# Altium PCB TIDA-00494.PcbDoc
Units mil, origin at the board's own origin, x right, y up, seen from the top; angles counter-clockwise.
Board outline 3140 x 3140 mil, 2 copper layers (Top Layer, Bottom Layer), stack 62 mil thick; 48 components, 40 nets, 138 pads, 74 vias.
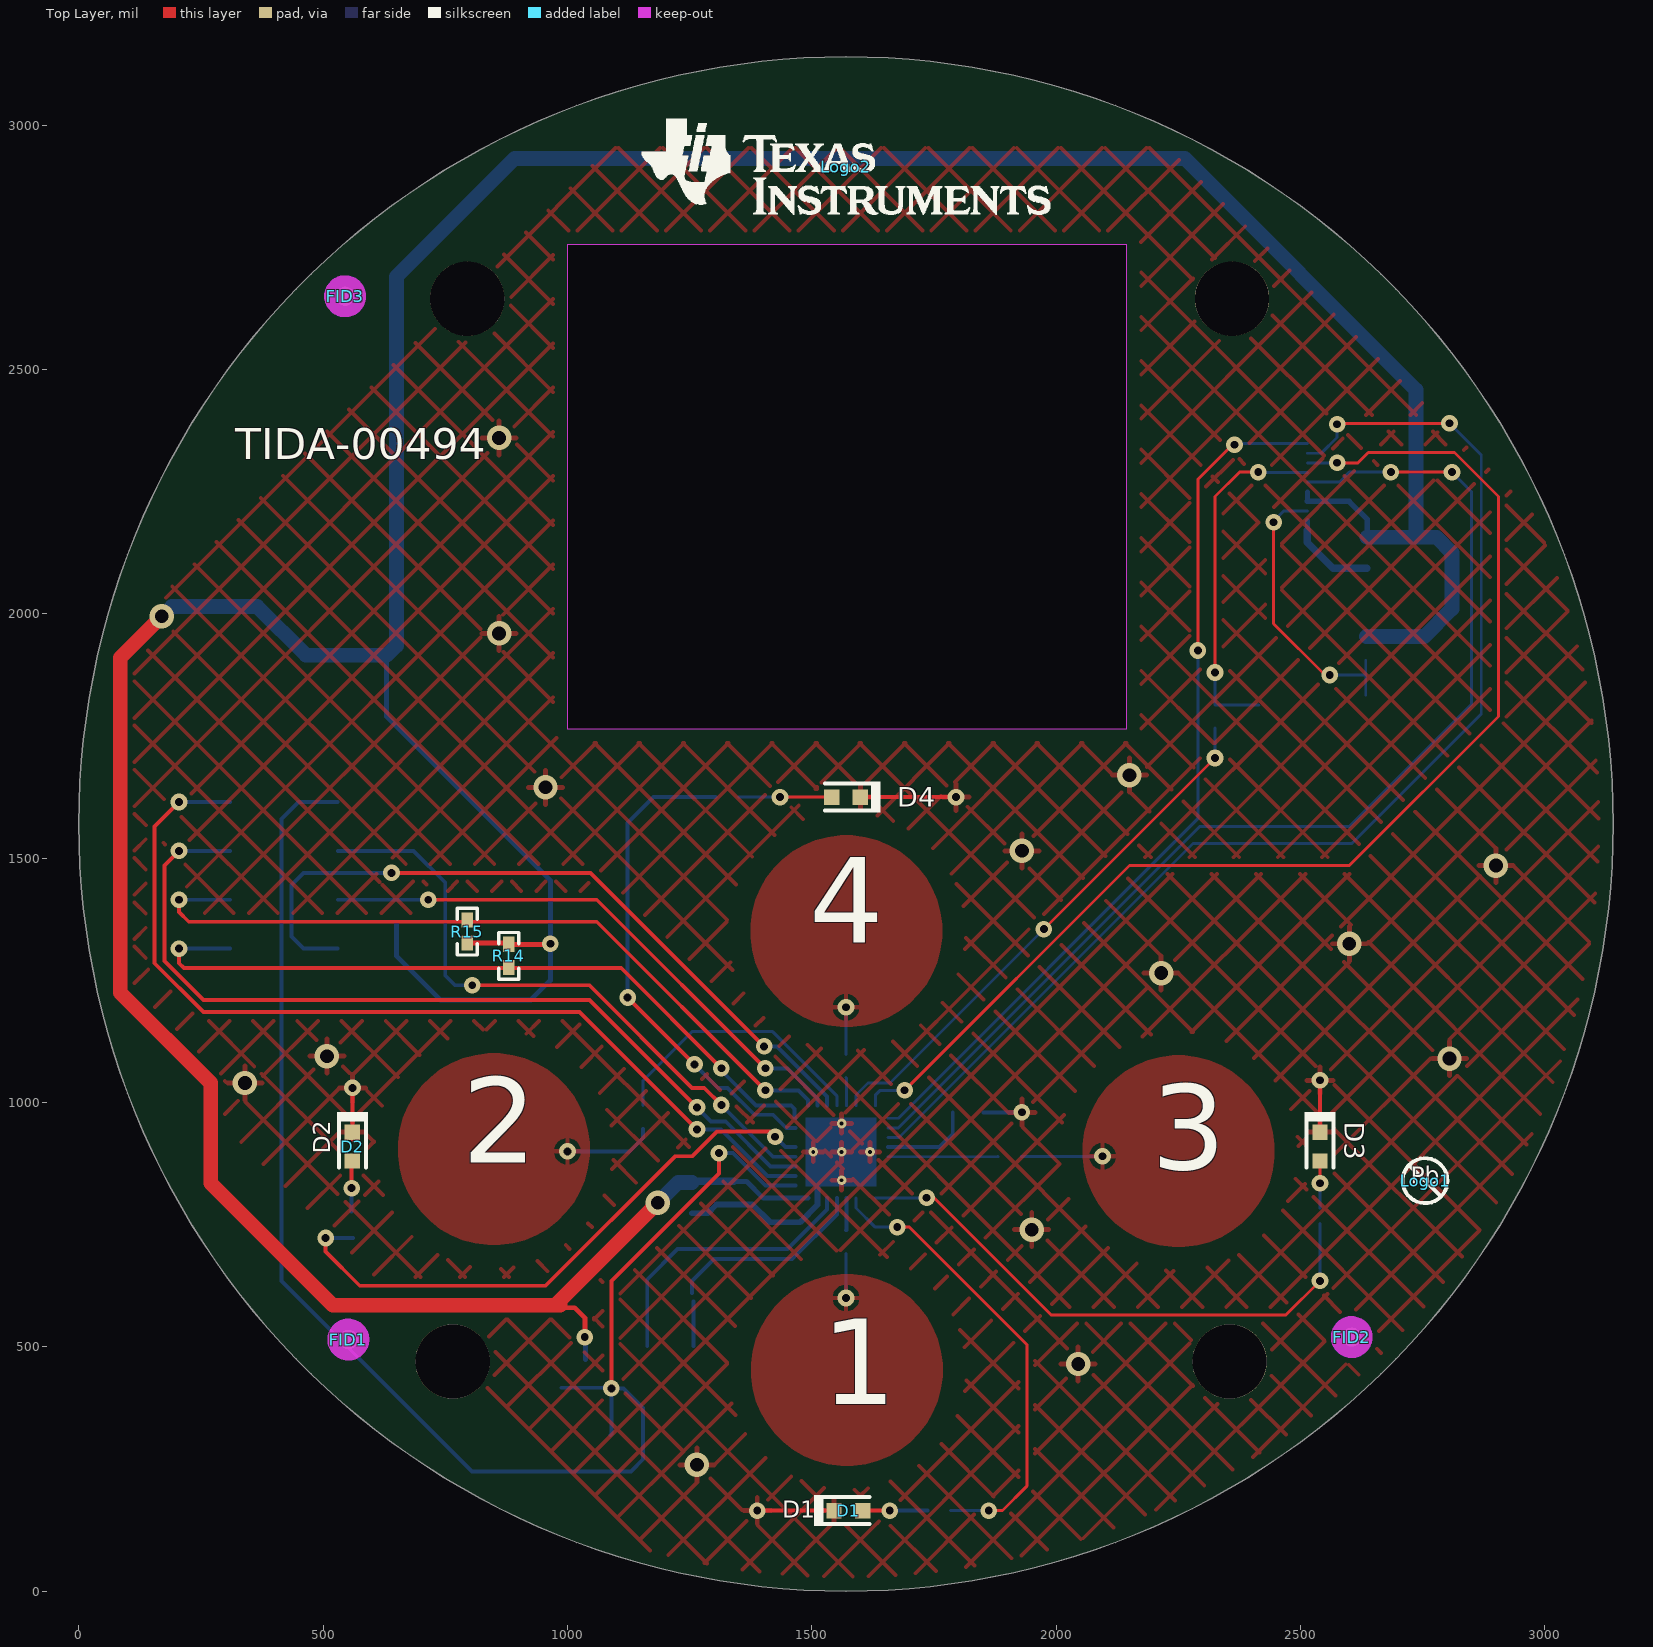
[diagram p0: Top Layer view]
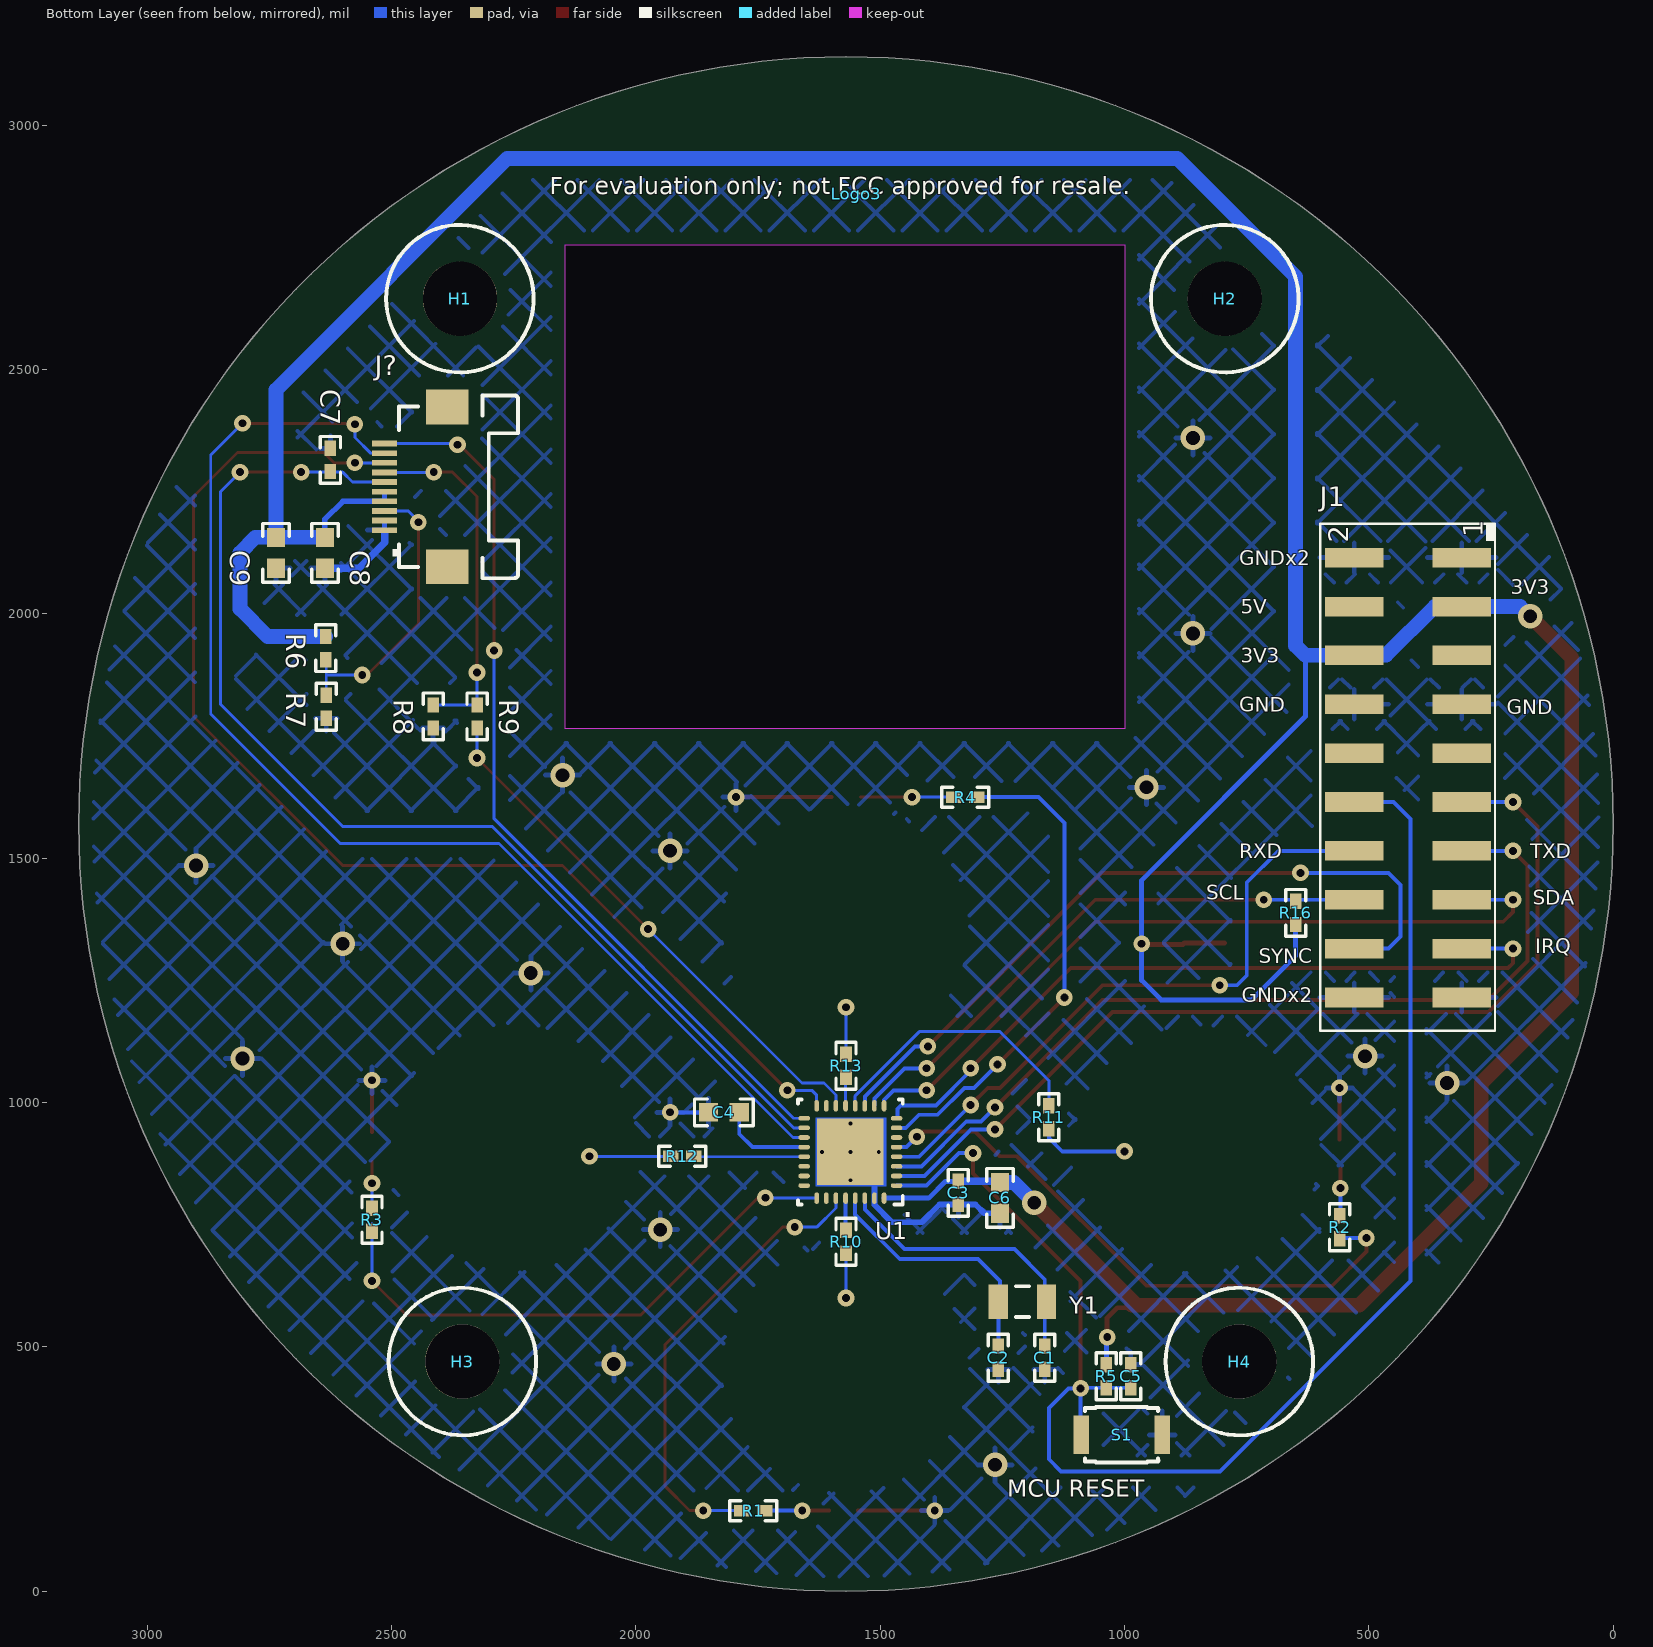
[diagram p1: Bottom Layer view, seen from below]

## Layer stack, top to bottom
Top Solder: solder mask 0.4, Solder Resist, Dk 3.5
Top Layer: signal copper 1.4
Dielectric1: core 59.2, FR-4, Dk 4.2
Bottom Layer: signal copper 1.4
Bottom Solder: solder mask 0.4, Solder Resist, Dk 3.5

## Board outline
1570,0 cw(c1570,1570) 0,1570 cw(c1570,1570) 1570,3140 cw(c1570,1570) 3140,1570 cw(c1570,1570)
cut-out: 1000,1765 2145,1765 2145,2755 1000,2755

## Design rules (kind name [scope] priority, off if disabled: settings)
AcuteAngle [All] p1: minimum=4.50000000000000E+0001 checktracksonly=FALSE
AssemblyTestPointUsage [All] p1: valid=2
BoardOutlineClearance BoardOutlineClearance_MountingHoles [OnCopper and InComponentClass('Mounting Holes')] p1: gap=40
BoardOutlineClearance BoardOutlineClearance_Poly [OnCopper and InPoly] p2: gap=25
BoardOutlineClearance [OnCopper and Not InComponentClass('Logo') and not InComponentClass('FiducialMark') and not InRegion(1000,500,4000,800)] p3: gap=25
Clearance Clearance_1 [InNamedPolygon('GND_L01_P076')] p1: gap=10 except(45: Poly-Poly)
Clearance Clearance_Keepouts [((IsTrack Or IsArc) And Not InPoly) And IsFree and IsKeepOut vs ((IsTrack Or IsArc) And Not InPoly) And IsFree and IsKeepOut] p2: gap=0
Clearance Clearance_Poly [InPolygon] p3: gap=25
Clearance [All] p4: gap=7.87
ComponentClearance ComponentClearance_MountingHoles_FiducialMarks [InComponentClass('Mounting Holes') vs InComponentClass('FiducialMark')] p1: gap=50 collisioncheckmode=3 verticalgap=10 showdistances=FALSE
ComponentClearance ComponentClearance_Shunt [InComponentClass('Header') vs InComponentClass('Shunt')] p2: gap=0 collisioncheckmode=3 verticalgap=0 showdistances=FALSE
ComponentClearance ComponentClearance_Logo [InComponentClass('Logo')] p3: gap=50 collisioncheckmode=3 verticalgap=10 showdistances=FALSE
ComponentClearance ComponentClearance_ScrewToNut [(HasFootprint('NY PMS 440 0025 PH')) vs (HasFootprint('Keystone_1902C'))] p4: gap=5 collisioncheckmode=3 verticalgap=10 showdistances=FALSE
ComponentClearance ComponentClearance_MountingHoles [InComponentClass('Mounting Holes')] p5: gap=250 collisioncheckmode=3 verticalgap=100000 showdistances=FALSE
ComponentClearance ComponentClearance_SmallPassives [HasFootprint('0201*') or HasFootprint('0402*') or HasFootprint('0508') or HasFootprint('0603*') or HasFootprint('0612') or HasFootprint('0805*') or HasFootprint('0815*') or HasFootprint('0830*') or HasFootprint('1206*') or HasFootprint('1210*') or HasFootprint('1808*') or HasFootprint('1812*') or HasFootprint('1825*') or HasFootprint('2010*') or HasFootprint('2220*') or HasFootprint('2225*') or HasFootprint('2512*') or HasFootprint('2728*') or HasFootprint('3518*') vs HasFootprint('0201*') or HasFootprint('0402*') or HasFootprint('0508') or HasFootprint('0603*') or HasFootprint('0612') or HasFootprint('0805*') or HasFootprint('0815*') or HasFootprint('0830*') or HasFootprint('1206*') or HasFootprint('1210*') or HasFootprint('1808*') or HasFootprint('1812*') or HasFootprint('1825*') or HasFootprint('2010*') or HasFootprint('2220*') or HasFootprint('2225*') or HasFootprint('2512*') or HasFootprint('2728*') or HasFootprint('3518*')] p6: gap=14.96 collisioncheckmode=3 verticalgap=10 showdistances=FALSE
ComponentClearance ComponentClearance_THtoSMT [IsThruComponent vs IsSMTComponent] p7: gap=40 collisioncheckmode=3 verticalgap=30 showdistances=FALSE
ComponentClearance ComponentClearance_THtoTH [IsThruComponent vs IsThruComponent] p8: gap=30 collisioncheckmode=3 verticalgap=30 showdistances=FALSE
ComponentClearance [All] p9: gap=30 collisioncheckmode=3 verticalgap=10 showdistances=FALSE
DiffPairsRouting [All] p1: maxlimit=100 minlimit=10 mostfreqgap=10 toplayer_minwidth=15 toplayer_maxwidth=15 toplayer_prefwidth=15 bottomlayer_minwidth=15 bottomlayer_maxwidth=15 bottomlayer_prefwidth=15 maxuncoupledlength=1000
FabricationTestPointUsage TestPointUsage [All] p1: valid=2 allowmultiple=FALSE
FabricationTestpoint Testpoint [All] p1: side=3 testpointundercomponent=TRUE minsize=40 maxsize=100 preferedsize=60 minholesize=0 maxholesize=40 preferedholesize=32 testpointgrid=1 allowsidetop=TRUE allowsidebottom=TRUE usegrid=TRUE gridtolerance=0.01
FanoutControl Fanout_LCC [IsLCC] p1: bgadir=Out bgaviamode=Centered fanoutstyle=Auto fanoutdirection=Alternating viagrid=1 // Fanout_LCC (Default Rule)
FanoutControl Fanout_BGA [IsBGA] p2: bgadir=Out bgaviamode=Centered fanoutstyle=Auto fanoutdirection=Alternating viagrid=1 // Fanout_BGA (Default Rule)
FanoutControl Fanout_Default [All] p4: bgadir=Out bgaviamode=Centered fanoutstyle=Auto fanoutdirection=Alternating viagrid=1 // Fanout_Default (Default Rule)
FanoutControl Fanout_Small [(CompPinCount < 5)] p5: bgadir=Out bgaviamode=Centered fanoutstyle=Auto fanoutdirection=OutThenIn viagrid=1 // Fanout_Small (Default Rule)
Height [All] p1 off: minheight=0 maxheight=1000 prefheight=500
HoleSize [All] p1: absolutevalues=TRUE maxlimit=251 minlimit=7.87 maxpercent=80.000 minpercent=20.000
MinimumAnnularRing MinimumAnnularRing_ThermalPadVias [IsVia and InAnyComponent] p1: minimumring=5.91
MinimumAnnularRing [All] p2: minimumring=8
MinimumSolderMaskSliver MinimumSolderMaskSliver_Logo [InComponentClass('Logo') vs InComponentClass('Logo')] p1: minsoldermaskwidth=0.7
MinimumSolderMaskSliver [All] p2: minsoldermaskwidth=3.94
PlaneConnect [All] p1: planeconnectstyle=Relief reliefexpansion=10 reliefentries=4 reliefconductorwidth=10 reliefairgap=10
PolygonConnect [All] p1: connectstyle=Relief reliefconductorwidth=10 reliefentries=4 polygonreliefangle="90 Angle" airgapwidth=10
RoutingVias ThermalPadVias [IsVia and InAnyComponent] p1: holewidth=7.87 width=19.68 viastyle="Through Hole" minholewidth=7.87 minwidth=19.68 maxholewidth=12.99 maxwidth=23.62
RoutingVias [All] p2: holewidth=16 width=34 viastyle="Through Hole" minholewidth=7.87 minwidth=26 maxholewidth=40 maxwidth=65
SilkToBoardRegionClearance [Not ((IsComment or IsDesignator) And (Hide <> 'False')) and not InRegion(1000,500,4000,800)] p1:
SilkToSilkClearance SilkToSilkClearance_Pb-FreeLogo [(HasFootprint('Pb-Free_Overlay_Medium') OR HasFootprint('Pb-Free_Overlay_Small')) vs (HasFootprint('Pb-Free_Overlay_Medium') OR HasFootprint('Pb-Free_Overlay_Small'))] p1: silktosilkclearance=0
SilkToSilkClearance [All] p2: silktosilkclearance=4
SilkToSolderMaskClearance SilkToComponentPadClearance [IsPad and InAnycomponent] p1: minsilkscreentomaskgap=5 clearancetoexposedcopper=TRUE
SilkToSolderMaskClearance "Silk to Solder Mask Opening" [All] p2: minsilkscreentomaskgap=4 clearancetoexposedcopper=FALSE
SolderMaskExpansion [All] p1: expansion=1.97
Width [All] p1: maxlimit=100 minlimit=6 preferedwidth=10 checkconnectedcopper=TRUE
14 further rules are at their usual default settings.

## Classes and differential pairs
net class R16_Nets: MSP_SCL VCC_MSP
net class R15_Nets: MSP_SDA VCC_MSP
net class R14_Nets: MSP_IRQ VCC_MSP
component class FiducialMark: FID1 FID2 FID3
component class TIDA-00494_Hardware: FID1 FID2 FID3 H1 H2 H3 H4 Logo1 Logo2 Logo3 ZZ1 ZZ2 ZZ3 ZZ4
net class Y1_Nets: XIN XOUT
net class U1_Nets: DISP_CLK DISP_CS DISP_EN DISP_EXTCOMIN DISP_SI EZFET_SBWTCK_TST EZFET_SBWTDIO_RST GND MSP_IRQ MSP_RXD MSP_SCL MSP_SDA MSP_SYNC MSP_TXD NetR10_1 NetR11_1 NetR12_1 NetR13_1 P1.0/LED4 P1.6/LED2 P2.7/LED3 P3.2/LED1 VCC_MSP VREG XIN XOUT
net class S1_Nets: EZFET_SBWTDIO_RST GND
net class R5_Nets: EZFET_SBWTDIO_RST VCC_MSP
net class R4_Nets: NetD4_1 P1.0/LED4
net class R3_Nets: NetD3_1 P2.7/LED3
net class C7_Nets: DISP_EN GND
net class J1_Nets: EZFET_RXD EZFET_SBWTCK_TST EZFET_SBWTDIO_RST EZFET_TXD GND MSP_IRQ MSP_RXD MSP_SCL MSP_SDA MSP_SYNC MSP_TXD VCC_5V VCC_METERED VCC_MSP
net class D2_Nets: GND NetD2_1
net class D1_Nets: GND NetD1_1
net class C2_Nets: GND XOUT
net class C5_Nets: EZFET_SBWTDIO_RST GND
net class C4_Nets: GND VREG
net class C3_Nets: GND VCC_MSP
net class C6_Nets: GND VCC_MSP
net class C1_Nets: GND XIN
component class TIDA-00494_Schematic: C1 C2 C3 C4 C5 C6 C7 C8 C9 D1 D2 D3 D4 J1 J? R1 R2 R3 R4 R5 R6 R7 R8 R9 R10 R11 R12 R13 R14 R15 R16 S1 U1 Y1
component class AssemblyNote: ZZ1 ZZ2 ZZ3 ZZ4
component class Logo: Logo2
net class C8_Nets: GND VCC_MSP
net class C9_Nets: GND VCC_MSP
net class D3_Nets: GND NetD3_1
net class D4_Nets: GND NetD4_1
net class J?_Nets: DISP_CLK DISP_CS DISP_EN DISP_SI GND NetJ?_3 NetJ?_7 VCC_MSP
net class R1_Nets: NetD1_1 P3.2/LED1
pad class "Through Hole": C5-2 D1-2 D2-2 J2-19 J2-20 TP4-1
net class R2_Nets: NetD2_1 P1.6/LED2
net class R6_Nets: NetJ?_3 VCC_MSP
net class R7_Nets: GND NetJ?_3
net class R8_Nets: GND NetJ?_7
net class R9_Nets: DISP_EXTCOMIN NetJ?_7
net class R10_Nets: BUTTON1 NetR10_1
net class R11_Nets: BUTTON2 NetR11_1
net class R12_Nets: BUTTON3 NetR12_1
net class R13_Nets: BUTTON4 NetR13_1

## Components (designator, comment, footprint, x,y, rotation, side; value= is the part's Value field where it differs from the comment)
C1 "GRM1555C1H220JA01D" 0402 1163.21,477.72 r270 bottom
C2 "GRM1555C1H220JA01D" 0402 1258.21,477.72 r270 bottom
C3 "C1005X5R1A104K" 0402 1340,815 r270 bottom
C4 "C1608X5R1A105K" 0603 1820,980 r0 bottom
C5 "C1005X7R1H102K" 0402 987.36,440 r90 bottom
C6 "C0603C475K8PACTU" 0603 1255,805 r270 bottom
C7 "C1005X5R1A104K" 0402 2625,2315 r90 bottom
C8 "C1608X5R1A105K" 0603 2636.3,2125 r90 bottom
C9 "C1608X5R1A105K" 0603 2736.3,2125 r90 bottom
D1 "LTST-C190GKT" LED_LTST-C190 1575,165 r180 top
D2 "LTST-C190GKT" LED_LTST-C190 560,910 r90 top
D3 "LTST-C190GKT" LED_LTST-C190 2540,910 r90 top
D4 "LTST-C190GKT" LED_LTST-C190 1570,1625 r0 top
FID1 "Fiducial" Fiducial10-20 551.67,515 r90 top
FID2 "Fiducial" Fiducial10-20 2605,520 r0 top
FID3 "Fiducial" Fiducial10-20 545,2650 r90 top
H1 "4826" KEYSTONE_4826 2360,2645 r90 bottom
H2 "4826" KEYSTONE_4826 795,2645 r90 bottom
H3 "4826" KEYSTONE_4826 2355,470 r90 bottom
H4 "4826" KEYSTONE_4826 765,470 r90 bottom
J1 "SSW-110-22-F-D-VS-K" CONN_SSW-110-22-F-D-VS-K 420,1665 r90 bottom
J? "FH12A-10S-0.5SH(55)" Hirose_FH12A-10S-0_5SH[55] 2450.1,2260.04 r90 bottom
Logo1 "Pb-Free Symbol" Pb-Free_Overlay_Small 2755,840 r0 top
Logo2 "Texas Instruments" TI_Stacked_Overlay_Small 1570,2915 r0 top
Logo3 "FCC disclaimer" FCC_disclaimer 1548.75,2860 r180 bottom
R1 "CRCW0402390RJNED" 0402 1760,165 r0 bottom
R2 "CRCW0402390RJNED" 0402 560,745 r270 bottom
R3 "CRCW0402390RJNED" 0402 2540,760 r270 bottom
R4 "CRCW0402390RJNED" 0402 1326.2,1625 r180 bottom
R5 "CRCW040247K0JNED" 0402 1037.36,440 r90 bottom
R6 "CRCW040247K0JNED" 0402 2635,1930 r90 bottom
R7 "CRCW04020000Z0ED" 0402 2633.59,1810 r90 bottom
R8 "CRCW04020000Z0ED" 0402 2415,1790 r90 bottom
R9 "CRCW04020000Z0ED" 0402 2325,1790 r90 bottom
R10 "CRCW04021K00JNED" 0402 1570,715 r270 bottom
R11 "CRCW04021K00JNED" 0402 1155,970 r270 bottom
R12 "CRCW04021K00JNED" 0402 1905,890 r0 bottom
R13 "CRCW04021K00JNED" 0402 1570,1075 r90 bottom
R14 "CRCW040210K0JNED" 0402 880,1300 r90 top
R15 "CRCW04022K20JNED" 0402 795,1350 r270 top
R16 "CRCW04022K20JNED" 0402 650,1388 r270 bottom
S1 "SKRKAEE010" SW_SKRKAEE010 1005.55,320 r0 bottom
U1 "MSP430FR2633IRHB" RHB0032E 1561.06,898.94 r0 bottom locked
Y1 "FC-135 32.7680KA-A3" Epson_FC-135 1209,592.72 r0 bottom
ZZ1 "This Assembly Note is for PCB labels only" AssemblyNoteLabel -110,3680 r0 top
ZZ2 "These assemblies are ESD sensitive, ESD precautions shall be observed." AssemblyNote -110,3585 r0 top
ZZ3 "These assemblies must be clean and free from flux and all contaminants. Use of no clean flux is not acceptable." AssemblyNote -110,3480 r0 top
ZZ4 "These assemblies must comply with workmanship standards IPC-A-610 Class 2, unless otherwise specified." AssemblyNote -110,3380 r0 top

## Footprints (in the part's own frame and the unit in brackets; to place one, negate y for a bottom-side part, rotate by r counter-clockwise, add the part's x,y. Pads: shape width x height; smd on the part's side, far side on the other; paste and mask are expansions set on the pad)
0402 [mm] "0402 from SM-752 data"
  rect 0.8x0.6 smd: 1(-0.6,0) 2(0.6,0)
  silkscreen extent -1.22,-0.52 1.22,0.52, body extent -0.55,-0.3 0.55,0.3, height 0.6
0603 [mm] "0603 from SM-752 data"
  rect 1x0.95 smd: 1(-0.8,0) 2(0.8,0)
  silkscreen extent -1.52,-0.69 1.52,0.69, body extent -0.87,-0.47 0.87,0.47, height 0.85
AssemblyNote [mil] "Assembly Note"
AssemblyNoteLabel [mil] "Assembly Note for PCB Labels"
CONN_SSW-110-22-F-D-VS-K [mil]
  rect 40x120 smd: 1(450,-110) 2(450,110) 3(350,-110) 4(350,110) 5(250,-110) 6(250,110) 7(150,-110) 8(150,110) 9(50,-110) 10(50,110) 11(-50,-110) 12(-50,110) 13(-150,-110) 14(-150,110) 15(-250,-110) 16(-250,110) 17(-350,-110) 18(-350,110) 19(-450,-110) 20(-450,110)
  silkscreen extent -518,-178 520,179, body extent -510,-155 500,155, height 435
Epson_FC-135 [mm] "SMD, 2-Leads, Body 3.2x1.5mm"
  rect 1x1.8 smd: 1(-1.25,0) 2(1.25,0)
  silkscreen extent -0.35,-0.8 0.35,0.8, body extent -1.65,-0.8 1.65,0.8, height 0.9
FCC_disclaimer [mil]
Fiducial10-20 [mm]
  round 1 smd mask+0.5: 1(0,0)
  Top Layer keep-out circle w1.178: c0,0 r0.5
Hirose_FH12A-10S-0_5SH[55] [mm] "FFC Connector , Top, 0.5mm, 10x1, R/A, SMT"
  rect 0.3x1.3 smd: 1(-2.254,1.625) 2(-1.754,1.625) 3(-1.254,1.625) 4(-0.754,1.625) 5(-0.253,1.625) 6(0.246,1.625) 7(0.746,1.625) 8(1.246,1.625) 9(1.746,1.625) 10(2.247,1.625)
  rect 1.8x2.2 smd: MP1(-4.15,-1.625) MP2(4.15,-1.625)
  silkscreen extent -4.75,-5.31 4.75,1.22, body extent -4.75,-5.31 4.75,1.69, height 2
KEYSTONE_4826 [mil] "HEX STANDOFF 6-32 NYLON 1750 mil"
  round 1 on Mech4: 0(0,0)
  round 152 hole 152 unplated: MH(0,0)
  silkscreen extent -151,-151 151,151, body extent -144,-125 144,125, height 1751
LED_LTST-C190 [mm] "Lite-On"
  rect 0.8x0.8 smd: 1(-0.75,0) 2(0.75,0)
  silkscreen extent -1.1,-0.8 1.8,0.8, body extent -0.85,-0.45 0.85,0.45, height 0.9
Pb-Free_Overlay_Small [mil]
  silkscreen extent -46,-46 46,46
RHB0032E [mm] "QFN, 32-Leads, Body 5x5mm, Pitch 0.5mm, Thermal Pad 3.45x3.45mm, TI Recommended"
  oval 0.6x0.24 smd: 1(-2.4,1.75) 2(-2.4,1.25) 3(-2.4,0.75) 4(-2.4,0.25) 5(-2.4,-0.25) 6(-2.4,-0.75) 7(-2.4,-1.25) 8(-2.4,-1.75) 17(2.4,-1.75) 18(2.4,-1.25) 19(2.4,-0.75) 20(2.4,-0.25) 21(2.4,0.25) 22(2.4,0.75) 23(2.4,1.25) 24(2.4,1.75)
  oval 0.24x0.6 smd: 9(-1.75,-2.4) 10(-1.25,-2.4) 11(-0.75,-2.4) 12(-0.25,-2.4) 13(0.25,-2.4) 14(0.75,-2.4) 15(1.25,-2.4) 16(1.75,-2.4) 25(1.75,2.4) 26(1.25,2.4) 27(0.75,2.4) 28(0.25,2.4) 29(-0.25,2.4) 30(-0.75,2.4) 31(-1.25,2.4) 32(-1.75,2.4)
  rect 3.45x3.45 smd paste-1.725: 33(0,0)
  silkscreen extent -2.72,-2.73 2.72,2.73, body extent -2.57,-2.57 2.58,2.58, height 1.01
SW_SKRKAEE010 [mm] "Alps recommended land pattern"
  rect 0.8x2 smd: 1(-2.1,0) 2(2.1,0)
  silkscreen extent -1.9,-1.44 1.92,1.44, body extent -2.4,-1.45 2.4,1.45, height 1.96
TI_Stacked_Overlay_Small [mil]
  silkscreen extent -418,-98 418,98

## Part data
C1 C2: "CAP, CERM, 22 pF, 50 V, +/- 5%, C0G/NP0, 0402"
C3 C7: "CAP, CERM, 0.1uF, 10V, +/-10%, X5R, 0402"
C4 C8 C9: "CAP, CERM, 1 µF, 10 V, +/- 10%, X5R, 0603"
C5: "CAP, CERM, 1000pF, 50V, +/-10%, X7R, 0402"
C6: "CAP, CERM, 4.7 µF, 10 V, +/- 10%, X5R, 0603"
D1 D2 D3 D4: "LED, Green, SMD"
FID1 FID2 FID3: "Fiducial mark.  There is nothing to buy or mount."
H1 H2 H3 H4: "HEX STANDOFF 6-32 NYLON 1-3/4\""
J1: "Connector, Receptacle, 100mil, 10x2, Gold plated, SMD"
J?: "FFC Connector , Top, 0.5mm, 10x1, R/A, SMT"
Logo1: library part Pb-Free
Logo2: library part TI_Logo, "Texas Instrument Corporate Signature"
Logo3: library part FCC_disclaimer, "FCC_disclaimer"
R1 R2 R3 R4: "RES, 390 ohm, 5%, 0.063W, 0402"
R5: "RES, 47k ohm, 5%, 0.063W, 0402"
R6: "RES, 47 k, 5%, 0.063 W, 0402"
R7 R8 R9: "RES, 0, 5%, 0.063 W, 0402"
R10 R11 R12 R13: "RES, 1.0 k, 5%, 0.063 W, 0402"
R14: "RES, 10 k, 5%, 0.063 W, 0402"
R15 R16: "RES, 2.2 k, 5%, 0.063 W, 0402"
S1: "Switch, Push Button, SMD"
U1: "MSP430 Captivate Microcontroller"
Y1: "Crystal, 32.768 KHz, 12.5 pF, SMD"
ZZ1: library part AssemblyNoteLabel
ZZ2 ZZ3 ZZ4: library part AssemblyNote

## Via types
v1: diameter 34, hole 16, Top Layer to Bottom Layer, 49 vias
v2: diameter 50, hole 28, Top Layer to Bottom Layer, 16 vias
v3: diameter 19.68, hole 7.87, Top Layer to Bottom Layer, 5 vias
v4: diameter 34, hole 16, Top Layer to Bottom Layer, tented both sides, 4 vias

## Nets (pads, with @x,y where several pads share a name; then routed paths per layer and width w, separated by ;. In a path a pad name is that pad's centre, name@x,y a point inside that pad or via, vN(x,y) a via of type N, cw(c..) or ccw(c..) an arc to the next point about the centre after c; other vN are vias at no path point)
BUTTON1: R10.2 | length 91.4
  Bottom Layer w6: v4(1570,600) R10.2
BUTTON2: R11.2 | length 185.2
  Bottom Layer w8: v4(1000,900) 1127.41,900 1155,927.59 R11.2
BUTTON3: R12.2 | length 166.4
  Bottom Layer w6: R12.2 v4(2095,890)
BUTTON4: R13.2 | length 96.4
  Bottom Layer w6: R13.2 v4(1570,1195)
DISP_CLK: J?.10 U1.17 | length 1837.6
  Top Layer w6: v1(2290,1925) 2290,2275 2360.94,2345.94 v1(2365,2345.94)
  Bottom Layer w6: U1.17 1677.18,967.83 2290,1580.66 v1(2290,1925) ; v1(2365,2345.94) 2365,2346.89 2366.56,2348.44 J?.10@2514.01,2348.44
DISP_CS: J?.8 U1.16 | length 2504.7
  Top Layer w6: v1(1690,1025) 2150,1485 2600,1485 2905,1790 2905,2240.25 2815.25,2330 2638.87,2330 2617.95,2309.07 v1(2575,2309.07)
  Bottom Layer w6: U1.16 1629.96,1014.96 1640,1025 v1(1690,1025) ; J?.8@2514.01,2309.07 v1(2575,2309.07)
DISP_EN: C7.1 J?.6 U1.18 | length 2349.5
  Top Layer w6: v1(2685,2290) v1(2810,2290)
  Bottom Layer w6: U1.18 1677.11,948.15 2293.97,1565 2600,1565 2850,1815 2850,2250 v1(2810,2290) ; J?.6@2514.01,2269.7 2579.7,2269.7 2600,2290 v1(2685,2290)
DISP_EXTCOMIN: R9.1 U1.14 | length 1103.5
  Top Layer w6: v1(1975,1355) 2315,1695 v1(2325,1705)
  Bottom Layer w6: U1.14 1590.59,1015.59 1615,1040 1660,1040 1970,1350 v1(1975,1355) ; v1(2325,1705) R9.1
DISP_SI: J?.9 U1.19 | length 2527.3
  Top Layer w6: v1(2575,2387.93) 2577.07,2390 v1(2805,2390)
  Bottom Layer w6: U1.19 1678.46,928.46 2280,1530 2605,1530 2870,1795 2870,2325 v1(2805,2390) ; J?.9@2514.01,2328.76 2542.61,2328.76 2575,2361.15 v1(2575,2387.93)
EZFET_RXD: J1.10
EZFET_SBWTCK_TST: J1.11 U1.2 | length 1947.6
  Top Layer w8: v1(205,1615) 155,1565 155,1285 255,1185 1025,1185 v1(1265,945)
  Bottom Layer w8: v1(205,1615) J1.11 ; v1(1265,945) 1313.94,945 1409.22,849.72 U1.2
EZFET_SBWTDIO_RST: C5.1 J1.12 R5.1 S1.2 U1.1 | length 3135
  Top Layer w8: v1(1090,415) 1090,635 1310,855 v1(1310,896.57)
  Bottom Layer w8: J1.12 450,1615 415,1580 415,635 805,245 1130,245 1155,270 1155,375 1115,415 v1(1090,415) ; C5.1 R5.1 1088.62,416.38 v1(1090,415) ; S1.2 1090,321.77 v1(1090,415) ; v1@1305,896.57 v1(1310,896.57) v1@1319.1,896.57 ; v1@1320,895.67 v1@1319.1,896.57 ; U1.1 1404.96,830.04 1338.43,896.57 v1@1319.1,896.57
EZFET_TXD: J1.9
GND: C1.2 C2.2 C3.2 C4.2 C5.2 C6.2 C7.2 C8.1 C9.1 D1.2 D2.2 D3.2 D4.2 J1.1 J1.2 J1.7 J1.8 J1.19 J1.20 J?.1 J?.2 R7.1 R8.1 S1.1 U1.31 U1.33 | length 1257.2
  Top Layer w8: D2.2@560,924.53 v1(560,1030) ; v1(1388.5,165) D1.2 ; D4.2 v1(1795,1625) ; D3.2 v1(2540,1045.45)
  Bottom Layer w8: C4.2 v1(1930,980)
  Bottom Layer w10: J?.1@2514.01,2171.28 J?.2@2514.01,2190.96
  Bottom Layer w12: C6.2 1287.32,773.5 1305.2,791.38 C3.2 1378.62,791.38 1415,755 1476.11,755 1511.85,790.74 U1.31 1511.85,849.72 v3(1561.06,898.94)
  Bottom Layer w15: v3(1619.13,898.94) U1.33@1622.32,898.94 ; J?.1@2514.01,2171.28 2514.01,2145.99 2566.5,2093.5 C8.1
  other v2: 1265,258.56 2045,465 1950,740 340,1040 2805,1090 507.83,1095 2215,1265 2600,1325 2900,1485 1930,1515 955,1645 2150,1670 860,1960 860,2360
  other v3: 1561.06,840.87 1502.99,898.94 1561.06,957.01
MSP_IRQ: J1.17 R14.1 U1.8 | length 1541.3
  Top Layer w8: v1(205,1315) 205,1285 215,1275 1110,1275 v1(1315,1070)
  Bottom Layer w8: v1(205,1315) J1.17 ; v1(1315,1070) 1315,1065 1385.9,994.1 1458.03,994.1 1465,987.13 1465,969.41 U1.8
MSP_RXD: J1.14 U1.4 | length 1293
  Top Layer w8: v1(805,1240) 1045,1240 1255,1030 1280,1030 v1(1315,995)
  Bottom Layer w8: J1.14 685,1515 750,1450 750,1260 770,1240 v1(805,1240) ; v1@1325,985 1420.91,889.09 U1.4
MSP_SCL: J1.16 R16.1 U1.10 | length 1165.1
  Top Layer w8: v1(715,1415) 1060,1415 v1(1405,1070)
  Bottom Layer w8: J1.16 v1(715,1415) ; v1(1405,1070) 1450,1070 1511.85,1008.15 U1.10
MSP_SDA: J1.15 R15.1 U1.9 | length 1601.6
  Top Layer w8: v1(205,1415) 205,1390 225,1370 1060,1370 v1(1405,1025)
  Bottom Layer w8: v1(205,1415) J1.15 ; v1@1405,1011.85 v1(1405,1025) 1472.55,1025 1492.17,1005.39 U1.9
MSP_SYNC: J1.18 U1.11 | length 1525.8
  Top Layer w8: v1(640,1470) 1047.5,1470 1052.5,1465 v1(1402.5,1115)
  Bottom Layer w8: J1.18 460,1315 435,1340 435,1445 455,1465 460,1470 v1(640,1470) ; v1(1402.5,1115) 1428.97,1115 1531.54,1012.43 U1.11
MSP_TXD: J1.13 U1.3 | length 1813.2
  Top Layer w8: v1(205,1515) 175,1485 175,1290 255,1210 1045,1210 v1(1265,990)
  Bottom Layer w8: v1(205,1515) J1.13 ; v1@1270,990 v1(1265,990) 1293.87,961.13 1323.87,961.13 1415.59,869.41 U1.3
NetD1_1: D1.1 R1.1 | length 131.9
  Top Layer w8: D1.1 v1(1659.55,165)
  Bottom Layer w8: v1(1659.55,165) R1.1
NetD2_1: D2.1 R2.1 | length 86.3
  Top Layer w8: v1(558.21,825) 558.21,863.68
  Bottom Layer w8: R2.1@558.21,777.38 v1(558.21,825)
NetD3_1: D3.1 R3.1 | length 96.9
  Top Layer w6: v1(2540,835) D3.1
  Bottom Layer w6: R3.1 v1(2540,835)
NetD4_1: D4.1 R4.1 | length 190.7
  Top Layer w6: v1(1435,1625) D4.1
  Bottom Layer w6: R4.1 v1(1435,1625)
NetJ?_3: J?.3 R6.1 R7.2 | length 591
  Top Layer w6: v1(2445,2187.5) 2445,1980 2550,1875 v1(2560,1875)
  Bottom Layer w6: v1(2445,2187.5) 2445,2190 2465.65,2210.65 J?.3@2514.01,2210.65 ; v1(2560,1875) 2633.59,1875 ; R7.2 2633.59,1875 ; R6.1@2633.59,1904.97 2633.59,1875
NetJ?_7: J?.7 R8.2 R9.2 | length 726.6
  Top Layer w6: v1(2325,1880) 2325,2240 2375,2290 v1(2413.78,2290) v1@2415,2288.78
  Bottom Layer w6: v1(2325,1880) R9.2 R8.2 ; v1@2415,2289.39 J?.7@2514.01,2289.39
NetR10_1: R10.1 U1.28 | length 66.2
  Bottom Layer w8: R10.1 1570.91,739.53 U1.28
NetR11_1: R11.1 U1.12 | length 563.7
  Bottom Layer w6: R11.1 1155,1045 1255,1145 1420,1145 1551.22,1013.78 U1.12
NetR12_1: R12.1 U1.21 | length 226.2
  Bottom Layer w6: U1.21 1880.47,889.09 R12.1
NetR13_1: R13.1 U1.13 | length 58.3
  Bottom Layer w6: R13.1 1570.91,1050.47 U1.13
P1.0/LED4: R4.2 U1.7 | length 1012.6
  Top Layer w8: v1(1123.15,1215) v1(1260,1078.15)
  Bottom Layer w8: v1(1123.15,1215) 1123.15,1572.45 1175.7,1625 R4.2 ; v1(1260,1078.15) 1308.15,1030 1327.55,1030 1382.55,975 1420.83,975 1447.68,948.15 U1.7
P1.6/LED2: R2.2 U1.5 | length 1226
  Top Layer w8: v1@505,729.86 505,695 575,625 955,625 1220,890 1255,890 1305.83,940.83 1414.17,940.83 v1(1425,930)
  Bottom Layer w8: v1(505,722.89) R2.2@561.51,722.89 ; v1(1425,930) 1446.22,908.78 U1.5
P2.7/LED3: R3.2 U1.25 | length 1155.8
  Top Layer w6: v1(1735,805) 1750,805 1990,565 2470,565 v1(2540,635)
  Bottom Layer w6: U1.25 1630.51,805 v1(1735,805) ; v1(2540,635) R3.2 2540,752.17
P3.2/LED1: R1.2 U1.27 | length 952.3
  Top Layer w6: v1(1675,745) 1700,745 1940,505 1940,215 1890,165 v1(1862,165)
  Bottom Layer w6: U1.27 1590.59,784.41 1630,745 v1(1675,745) ; R1.2 v1(1862,165)
VCC_5V: J1.4
VCC_METERED: J1.5
VCC_MSP: C3.1 C6.1 C8.2 C9.2 J1.3 J1.6 J?.4 J?.5 R5.2 R6.2 R14.2 R15.2 R16.2 U1.32 | length 8961.6
  Top Layer w10: R15.2 877.24,1326.38 R14.2 963.62,1323.62 v1(965,1325) ; 980,580 1015,580 1035.55,559.45 v1(1035.55,520) ; 985,585 985,590
  Top Layer w30: v2(170,1995) 85,1910 85,1225 270,1040 270,835 520,585 975,585 ; 985,585 975,585 ; v2(1185,795) 975,585
  Bottom Layer w10: 630,1915 630,1790 965,1455 v1(965,1325) 965,1250 925,1210 740,1210 650,1300 R16.2 ; v1(1035.55,520) 1037.2,518.35 R5.2@1037.2,473.62 ; C3.1 1366.38,838.62 1400.55,804.45 U1.32 ; J?.4@2514.01,2231.93 J?.5@2514.01,2250.02
  Bottom Layer w11: J?.4 2599.63,2230.37 2636.3,2193.7 C8.2
  Bottom Layer w15: C6.1 1257.13,838.62 C3.1
  Bottom Layer w30: v2(170,1995) 190,2015 J1.3 365,2015 465,1915 J1.6 630,1915 650,1935 650,2690.04 891.87,2931.91 2263.09,2931.91 2736.3,2458.7 C9.2 ; v2(1185,795) 1226.5,836.5 C6.1 ; R6.2 2753.62,1953.62 2810,2010 2810,2125 2778.5,2156.5 C9.2 ; C8.2 C9.2
VREG: C4.1 U1.20 | length 188.3
  Bottom Layer w8: U1.20 1761.48,908.78 1788.5,935.8 C4.1
XIN: C1.1 U1.30 Y1.1 | length 587.5
  Bottom Layer w8: C1.1 1163.21,638.21 1225,700 1450,700 1531.54,781.54 U1.30
XOUT: C2.1 U1.29 Y1.2 | length 502.3
  Bottom Layer w8: Y1.2@1255,610 1255,635 1300,680 1460,680 1551.22,771.22 U1.29 ; C2.1 Y1.2
pads on no net: FID1.1 FID2.1 FID3.1 H1.0 H1.MH H2.0 H2.MH H3.0 H3.MH H4.0 H4.MH J?.MP1 J?.MP2 U1.6 U1.15 U1.22 U1.23 U1.24 U1.26

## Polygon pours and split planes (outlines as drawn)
BUTTON4 on Top Layer "BUTTON4_L01_P070" (solid, pour order 70): 1374.58,1350.68 ccw(c1570.58,1350.68) 1570.58,1154.68 ccw(c1570.58,1350.68) 1766.58,1350.68 ccw(c1570.58,1350.68) 1570.58,1546.68 ccw(c1570.58,1350.68)
BUTTON1 on Top Layer "BUTTON1_L01_P068" (solid, pour order 68): 1375.68,452.65 ccw(c1571.68,452.65) 1571.68,256.65 ccw(c1571.68,452.65) 1767.68,452.65 ccw(c1571.68,452.65) 1571.68,648.65 ccw(c1571.68,452.65)
BUTTON3 on Top Layer "BUTTON3_L01_P066" (solid, pour order 66): 2054.68,900.5 ccw(c2250.68,900.5) 2250.68,704.5 ccw(c2250.68,900.5) 2446.68,900.5 ccw(c2250.68,900.5) 2250.68,1096.5 ccw(c2250.68,900.5)
BUTTON2 on Top Layer "BUTTON2_L01_P064" (solid, pour order 64): 653.32,904.5 ccw(c849.32,904.5) 849.32,708.5 ccw(c849.32,904.5) 1045.32,904.5 ccw(c849.32,904.5) 849.32,1100.5 ccw(c849.32,904.5)
GND on Top Layer "GND_L01_P076" (hatched 45Degree grid 64 track 8, remove dead copper, pour order 76): 70,1182.03 1249.05,2.98 2222.39,2.98 2227.39,7.98 3132.39,912.98 3132.39,2047.98 2227.39,2952.98 1087.98,2952.98 70,1935
GND on Bottom Layer "GND_L02_P074" (hatched 45Degree grid 64 track 8, remove dead copper, pour order 74): 0,1030 1030,0 2245,0 2250,5 3155,910 3155,2045 2250,2950 965,2950 0,1985

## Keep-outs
Keep-Out Layer:
  text ".Layer_Name" at -73,-1708.49 h60

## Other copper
Top Layer:
  text ".Layer_Name" at -73,-1708.49 h60
Bottom Layer:
  region net GND: 1487.4,955.87 1487.4,968.86 1518.75,968.86 1632.4,968.86 1632.4,828.86 1487.4,828.86
  pour cut-out: 1315.84,1355.8 ccw(c1570.84,1355.8) 1570.84,1100.8 ccw(c1570.84,1355.8) 1825.84,1355.8 ccw(c1570.84,1355.8) 1570.84,1610.8 ccw(c1570.84,1355.8)
  pour cut-out: 597.47,905 ccw(c852.47,905) 852.47,650 ccw(c852.47,905) 1107.47,905 ccw(c852.47,905) 852.47,1160 ccw(c852.47,905)
  pour cut-out: 1316.25,453.98 ccw(c1571.25,453.98) 1571.25,198.98 ccw(c1571.25,453.98) 1826.25,453.98 ccw(c1571.25,453.98) 1571.25,708.98 ccw(c1571.25,453.98)
  pour cut-out: 1995,907.36 ccw(c2250,907.36) 2250,652.36 ccw(c2250,907.36) 2505,907.36 ccw(c2250,907.36) 2250,1162.36 ccw(c2250,907.36)
  text ".Layer_Name" at -73,-1708.49 h60

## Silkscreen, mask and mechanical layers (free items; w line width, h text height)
Top Overlay:
  text "TIDA-00494" at 320,2295 h108.27
  text "4" at 1495,1270 h300
  text "D2" at 515,895 h35 r90
  text "2" at 785,820 h300
  text "3" at 2195,805 h300
  text "1" at 1520,325 h300
  text "D1" at 1440,150 h35
  text ".Layer_Name" at -73,-1708.49 h60
Bottom Overlay:
  text "GNDx2" at 765,2100 h30
  text "3V3" at 210,2040 h30
  text "5V" at 762.5,2000 h30
  text "3V3" at 762.5,1900 h30
  text "GND" at 765,1800 h30
  text "GND" at 217.5,1795 h30
  text "TXD" at 170,1500 h30
  text "RXD" at 765,1500 h30
  text "SCL" at 832.64,1415 h30
  text "SDA" at 165,1405 h30
  text "IRQ" at 160,1305 h30
  text "SYNC" at 725,1285 h30
  text "GNDx2" at 760,1205 h30
  text "." at 1430,765 h60
  text "MCU RESET" at 1240,193.05 h35
  text ".Layer_Name" at -73,-1708.49 h60
Top Paste:
  text ".Layer_Name" at -73,-1708.49 h60
Bottom Paste:
  text ".Layer_Name" at -73,-1708.49 h60
Top Solder:
  text ".Layer_Name" at -73,-1708.49 h60
  text ".Layer_Name" at -73,-1708.49 h60
Bottom Solder:
  text ".Layer_Name" at -73,-1708.49 h60
Drill Guide:
  text ".Layer_Name" at -73,-1708.49 h60
M1 Board Outline:
  circle w10: c1570,1570 r1570
  lines w10: 0,1570 cw(c1570,1570) 1570,3140 cw(c1570,1570) 3140,1570 cw(c1570,1570) 1570,0 cw(c1570,1570) 0,1570 ; 1000,1765 1000,2755 2145,2755 2145,1765 1000,1765
  text ".Layer_Name" at -73,-1708.49 h60
M2 Board Dimensions:
  rectangle: -525,-1250 -150,-1125
  rectangle: -650,-1125 -525,-1000
  lines w7: -650,-1125 350,-1125 ; -525,-1250 -525,-1000 ; -400,-1250 -400,-1000 ; -150,-1250 -150,-1000 ; 100,-1250 100,-1000 ; -650,-1250 -650,-1000 350,-1000 350,-1250 -650,-1250
  text ".Layer_Name" at -73,-1708.49 h60
M3 3D STEP Top:
  text ".Layer_Name" at -73,-1708.49 h60
M4 3D STEP Bottom:
  text ".Layer_Name" at -73,-1708.49 h60
M5 Assembly Top:
  lines w10: -942,-1780.17 5658,-1780.17 ; -942,-1576.83 5660,-1576.83 ; -942,-1373.5 -942,-1983.5 3063,-1983.5 5660,-1983.5 5660,-1373.5 -941.5,-1373.5 -941.5,-1983.5 634,-1983.5 ; 1523,-1983.5 1523,-1373.5 ; 2790,-1576.83 2790,-1373.5 ; 3630,-1576.83 3630,-1373.5 ; 4252,-1990 4252,-1787.17
  text "COMPONENTS MARKED 'DNP' SHOULD NOT BE POPULATED." at 503.5,-1168.5 h60
  text "ASSEMBLY VARIANT:" at 503,-1284 h60
  text ".VariantName" at 1539,-1284 h60
  text "PCB VIEWED FROM TOP SIDE" at -878.5,-1505.67 h60
  text "BOARD #:" at 1598,-1505.67 h60
  text ".PRJ_Number" at 2143.5,-1505.67 h60
  text "REV:" at 2988,-1505.67 h60
  text ".PCB_Rev" at 3279.5,-1505.67 h60
  text "SVN REV:" at 3826,-1505.67 h60
  text ".VersionControl_RevNumber" at 4332,-1505.67 h60
  text "PLOT NAME =" at -878.5,-1914.34 h60
  text ".plot_File_Name" at -73,-1914.34 h60
  text "GENERATED    :" at 1600,-1914.34 h60
  text ".Print_Date" at 2469.5,-1914.34 h60
  text ".Print_Time" at 3198.5,-1914.34 h60
  text "TEXAS INSTRUMENTS" at 4463,-1914.34 h60
M6 Assembly Bottom:
  lines w10: -942.5,-1577.33 5659.5,-1577.33 ; -940.5,-1780.67 5659.5,-1780.67 ; 465.5,-1990.5 465.5,-1787.67 ; 1087.5,-1577.33 1087.5,-1374 ; 1927.5,-1577.33 1927.5,-1374 ; 3194.5,-1984 3194.5,-1374 ; 4083.5,-1984 5659,-1984 5659,-1374 -942.5,-1374 -942.5,-1984 1654.5,-1984 5659.5,-1984 5659.5,-1374
  text "COMPONENTS MARKED 'DNP' SHOULD NOT BE POPULATED." at 5452,-1168 h60
  text ".VariantName" at 4408,-1284 h60
  text "ASSEMBLY VARIANT:" at 5447,-1284 h60
  text ".VersionControl_RevNumber" at 385.5,-1506.17 h60
  text "SVN REV:" at 891.5,-1506.17 h60
  text ".PCB_Rev" at 1438,-1506.17 h60
  text "REV:" at 1729.5,-1506.17 h60
  text ".PRJ_Number" at 2574,-1506.17 h60
  text "BOARD #:" at 3119.5,-1506.17 h60
  text "PCB VIEWED FROM BOTTOM SIDE" at 5596,-1506.17 h60
  text "TEXAS INSTRUMENTS" at 254.5,-1914.84 h60
  text ".Print_Time" at 1519,-1914.84 h60
  text ".Print_Date" at 2248,-1914.84 h60
  text "GENERATED    :" at 3117.5,-1914.84 h60
  text ".plot_File_Name" at 4790.5,-1914.84 h60
  text "PLOT NAME =" at 5596,-1914.84 h60
M9 Title Sheet:
  drawing of 57 lines, arcs and shapes, not listed
  text "1" at 89.84,7186.5 h70
  text "2" at 2585.5,7186.5 h70
  text "3" at 5074.84,7186.5 h70
  text "4" at 7581.51,7186.5 h70
  text "5" at 10080.5,7186.5 h70
  text "6" at 12585.5,7186.5 h70
  text "A" at -1066.5,6043.5 h70
  text "A" at 13733.5,6043.5 h70
  text "B" at -1066.5,3663.5 h70
  text "B" at 13733.5,3663.5 h70
  text "C" at -1066.5,1288.5 h70
  text "C" at 13733.5,1288.5 h70
  text "PROJECT TITLE:" at 10693.5,-572.5 h45
  text ".PRJ_Title" at 10743.5,-705.83 h70
  text "DESIGNED FOR:" at 10693.5,-873.5 h45
  text ".PRJ_Customer" at 10743.5,-1013.5 h70
  text "D" at -1066.5,-1081.5 h70
  text "D" at 13733.5,-1081.5 h70
  text "FILE NAME:" at 10693.5,-1173.5 h45
  text ".PCB_File_Name_No_Path" at 10743.5,-1293.5 h70
  text "Texas Instruments (TI) and/or its licensors do not warrant the accuracy or completeness of this specification" at 5724,-1455.34 h45
  text "ENGINEER:" at 10693.5,-1463.5 h45
  text "LAYOUT BY:" at 12198.5,-1463.5 h45
  text "or any information contained therein. TI and/or its licensors do not warrant that this design will meet" at 5679.01,-1568 h45
  text ".PRJ_Engineer" at 10743.5,-1618.49 h70
  text ".PCB_Layout" at 12249,-1618.49 h70
  text "the specifications, will be suitable for your application or fit for any particular purpose, or will operate in" at 5679.01,-1680.67 h45
  text ".Layer_Name" at -73,-1708.49 h60
  text "ALTIUM DESIGNER VERSION:" at 12198.5,-1773.5 h45
  text "an implementation. TI and/or its licensors do not warrant that the design is production worthy. You should" at 5679.01,-1793.33 h45
  text "completely validate and test your design implementation to confirm the system functionality for your application." at 5724,-1906 h45
  text ".print_Scale" at 10743.5,-1906.83 h70
  text ".Application_BuildNumber" at 12249,-1906.83 h70
  text "1" at 89.84,-2113.5 h70
  text "2" at 2585.5,-2113.5 h70
  text "3" at 5074.84,-2113.5 h70
  text "4" at 7581.51,-2113.5 h70
  text "5" at 10080.5,-2113.5 h70
  text "6" at 12585.5,-2113.5 h70
M10 Fab Notes:
  drawing of 185 lines, arcs and shapes, not listed
  text "DESIGN INFORMATION" at 11731.02,5060 h60
  text "MIN. TRACK WIDTH:" at 11086.46,4880 h60
  text "6" at 12182.7,4880 h60
  text "MIL" at 12337.46,4880 h60
  text "MIN. CLEARANCE:" at 11086.46,4748 h60
  text "0.2" at 12122.7,4748 h60
  text "mm" at 12337.46,4748 h60
  text "MIN. VIA PAD SIZE:" at 11086.46,4616 h60
  text "30" at 12152.71,4616 h60
  text "MIL" at 12337.46,4616 h60
  text "0.05mm (2MIL)" at 11781.46,4474.29 h60
  text "MINIMUM ANNULAR RING" at 10757.23,4470 h60
  text "EXTERNAL" at 12489.46,4470 h60
  text "PER" at 10957.23,4352 h60
  text "IPC-D-275 CLASS 2 LEVEL C" at 11177.23,4352 h60
  text "MIL, HOLES" at 12665.46,4239.71 h60
  text "+/-" at 12273,4239 h60
  text "+/-" at 13127,4239 h60
  text "REGISTRATION TOLERANCES:" at 10757.23,4234 h60
  text "METAL" at 11957,4234 h60
  text "5" at 12533.2,4234 h60
  text "3" at 13366.2,4234 h60
  text "MIL" at 13482.46,4234 h60
  text "MATERIAL:" at 10682.46,4024.54 h60
  text "FR-4 High Tg" at 11668.9,3884.21 h60
  text "FR-408" at 11103.46,3875.64 h60
  text "X" at 11515.46,3875.64 h60
  text "OTHER" at 12591.46,3875.64 h60
  text "62 MIL (1.6mm) +/-10%" at 11423.56,3712.92 h60
  text "THICKNESS:" at 10757.23,3708.64 h60
  text "X" at 11295.4,3708.64 h60
  text "OTHER" at 12708.46,3708.64 h60
  text "TOLERANCE:" at 10757.23,3550.64 h60
  text "X" at 11596.53,3550.64 h60
  text "ANSI IPC-6012 TYPE 3 CLASS 2" at 11783.48,3550.64 h60
  text "OTHER +/-" at 11783.46,3394.64 h60
  text "BOW & TWIST:" at 10757.23,3237.64 h60
  text "X" at 11596.53,3237.64 h60
  text "ANSI IPC-6012 TYPE 3 CLASS 2" at 11783.48,3237.64 h60
  text "OTHER +/-" at 11783.46,3079.13 h60
  text "DRILLING:" at 10682.46,2940.64 h60
  text "REFERENCE:" at 10757.23,2823.64 h60
  text "X" at 11405.46,2823.64 h60
  text "AS SHOWN" at 11592.46,2823.64 h60
  text "X" at 12306.46,2823.64 h60
  text "NC_DRILL FILES" at 12443.46,2823.64 h60
  text "PTH MIN COPPER THICKNESS:" at 10757.23,2665.64 h60
  text "X" at 12107.46,2665.64 h60
  text "1MIL" at 12244.46,2665.64 h60
  text "OTHER" at 12741.46,2665.64 h60
  text "BOARD FINISH:" at 10682.46,2506.64 h60
  text "SILKSCREEN:" at 10837.68,2388.64 h60
  text "X" at 11786.46,2388.64 h60
  text "TOP" at 11912.46,2388.64 h60
  text "X" at 12296.46,2388.64 h60
  text "BOTTOM" at 12423.46,2388.64 h60
  text "SILKSCREEN COLOR:" at 10837.68,2221.64 h60
  text "X" at 11785.42,2221.64 h60
  text "WHITE" at 11912.46,2221.64 h60
  text "OTHER" at 12423.46,2221.64 h60
  text "SOLDER RESIST COLOR:" at 10837.68,2051.64 h60
  text "X" at 12520,1895 h60
  text "GREEN" at 11532.46,1892.44 h60
  text "BLUE" at 12123.46,1892.44 h60
  text "OTHER" at 12661.46,1892.44 h60
  text "GREEN" at 12960,1885 h200
  text "IMMERSION GOLD (ENIG)" at 11743.46,1703.92 h60
  text "ENEPIG" at 13081,1700.64 h60
  text "SURFACE FINISH:" at 10682.46,1699.64 h60
  text "X" at 11556.51,1699.64 h60
  text "IMM. TIN/SILVER OR EQUIV" at 11012,1542.64 h60
  text "OTHER" at 12443.46,1542.64 h60
  text "ARRAY/PANEL:" at 10682.46,1363.64 h60
  text "CUT AND TRIM PER MECH LAYER 1" at 11743.46,1359.35 h60
  text "N.C. ROUTE" at 11743.46,1207.64 h60
  text "X" at 12422.46,1207.64 h60
  text "V. SCORE" at 12609.46,1207.64 h60
  text "CERTIFICATION:" at 10682.46,1070.64 h60
  text "MATERIALS AND WORKMANSHIP FOR ALL PCBS" at 11407.46,1070.64 h60
  text "TO MEET OR EXCEED THE REQUIREMENTS OF:" at 11407.46,972.64 h60
  text "X" at 11033.96,836.13 h60
  text "ANSI IPC-A-600F CLASS ->" at 11172.96,836.13 h60
  text "X" at 12812.02,836.13 h60
  text "2" at 12930.96,836.14 h60
  text "1" at 12615.96,834.64 h60
  text "3" at 13284.96,834.64 h60
  text "X" at 11036.02,676.64 h60
  text "UL 94V-0" at 11172.96,676.64 h60
  text "X" at 11848.02,676.64 h60
  text "RoHS" at 11984.96,676.64 h60
  text "OTHER" at 12629.36,676.64 h60
  text "PER ORDER" at 13026.42,676.64 h60
  text "ADDITIONAL REQUIREMENTS:" at 10682.46,535.64 h60
  text "MICROSECTION:" at 10757.23,420.64 h60
  text "YES" at 11662.96,420.64 h60
  text "REQUIRED" at 12524.46,264.49 h60
  text "BARE BOARD ELEC. TEST:" at 10757.23,261.64 h60
  text "NONE" at 12062.96,261.64 h60
  text "X" at 12397.46,261.64 h60
  text "PER ORDER" at 13116.46,261.64 h60
  text "MANUFACTURER'S UL:" at 10757.23,104.64 h60
  text "RAIL" at 11922.96,100.35 h60
  text "METAL" at 12414.77,100.35 h60
  text "X" at 12790,100 h60
  text "SILK" at 12926.46,100.35 h60
  text ".Layer_Name" at -73,-1708.49 h60
M11 Gerber Information:
  lines w10: -942,-1780.17 5658,-1780.17 ; -942,-1576.83 5660,-1576.83 ; -942,-1373.5 -942,-1983.5 3063,-1983.5 5660,-1983.5 5660,-1373.5 -941.5,-1373.5 -941.5,-1983.5 634,-1983.5 ; 1523,-1983.5 1523,-1373.5 ; 2790,-1576.83 2790,-1373.5 ; 3630,-1576.83 3630,-1373.5 ; 4252,-1990 4252,-1787.17
  text "ALL ARTWORK VIEWED FROM TOP SIDE" at -878.5,-1505.67 h60
  text "BOARD #:" at 1598,-1505.67 h60
  text ".PRJ_Number" at 2143.5,-1505.67 h60
  text "REV:" at 2988,-1505.67 h60
  text ".PCB_Rev" at 3279.5,-1505.67 h60
  text "SVN REV:" at 3826,-1505.67 h60
  text ".VersionControl_RevNumber" at 4332,-1505.67 h60
  text "LAYER NAME =" at -878.5,-1708.49 h60
  text "PLOT NAME =" at -878.5,-1914.34 h60
  text ".plot_File_Name" at -73,-1914.34 h60
  text "GENERATED    :" at 1600,-1914.34 h60
  text ".Print_Date" at 2469.5,-1914.34 h60
  text ".Print_Time" at 3198.5,-1914.34 h60
  text "TEXAS INSTRUMENTS" at 4463,-1914.34 h60
M12 Stackup:
  drawing of 191 lines, arcs and shapes, not listed
  text "Layer" at 9095.58,6950 h60
  text "Name" at 9505.49,6950 h60
  text "Material" at 10435.23,6950 h60
  text "Thickness" at 11295,6950 h60
  text "Constant" at 11944.84,6950 h60
  text "Board Layer Stack" at 12514.7,6950 h60
  text "1" at 9095.58,6830 h60
  text "Top Overlay" at 9505.49,6830 h60
  text "2" at 9095.58,6710 h60
  text "Top Solder" at 9505.49,6710 h60
  text "Solder Resist" at 10435.23,6710 h60
  text "0.40mil" at 11295,6710 h60
  text "3.5" at 11944.84,6710 h60
  text "3" at 9095.58,6590 h60
  text "Top Layer" at 9505.49,6590 h60
  text "Copper" at 10435.23,6590 h60
  text "1.40mil" at 11295,6590 h60
  text "4" at 9095.58,6470 h60
  text "Dielectric1" at 9505.49,6470 h60
  text "FR-4" at 10435.23,6470 h60
  text "59.20mil" at 11295,6470 h60
  text "4.2" at 11944.84,6470 h60
  text "5" at 9095.58,6350 h60
  text "Bottom Layer" at 9505.49,6350 h60
  text "Copper" at 10435.23,6350 h60
  text "1.40mil" at 11295,6350 h60
  text "6" at 9095.58,6230 h60
  text "Bottom Solder" at 9505.49,6230 h60
  text "Solder Resist" at 10435.23,6230 h60
  text "0.40mil" at 11295,6230 h60
  text "3.5" at 11944.84,6230 h60
  text "7" at 9095.58,6110 h60
  text "Bottom Overlay" at 9505.49,6110 h60
  text ".Layer_Name" at -73,-1708.49 h60
M13 Component Bodies Top:
  text ".Layer_Name" at -73,-1708.49 h60
M14 Component Bodies Bottom:
  text ".Layer_Name" at -73,-1708.49 h60
M15 Courtyards Top:
  text ".Layer_Name" at -73,-1708.49 h60
M16 Courtyards Bottom:
  text ".Layer_Name" at -73,-1708.49 h60
Drill Drawing:
  lines w10: 6047.29,-932.5 6047.29,-915.83 6063.96,-899.17 6047.29,-882.5 6047.29,-865.83 6063.96,-865.83 6080.62,-882.5 6097.29,-865.83 6113.96,-865.83 6113.96,-882.5 6097.29,-899.17 6113.96,-915.83 6113.96,-932.5 6097.29,-932.5 6080.62,-915.83 6063.96,-932.5 6047.29,-932.5 ; 6047.29,-765.83 6063.96,-765.83 6063.96,-782.5 6097.29,-782.5 6097.29,-765.83 6113.96,-765.83 6113.96,-732.5 6097.29,-732.5 6097.29,-715.83 6063.96,-715.83 6063.96,-732.5 6047.29,-732.5 6047.29,-765.83 ; 6047.29,-482.5 6113.96,-482.5 6113.96,-415.83 6047.29,-415.83 6047.29,-482.5 ; 6060.62,-919.17 6060.62,-909.17 6070.62,-899.17 6060.62,-889.17 6060.62,-879.17 6070.62,-879.17 6080.62,-889.17 6090.62,-879.17 6100.62,-879.17 6100.62,-889.17 6090.62,-899.17 6100.62,-909.17 6100.62,-919.17 6090.62,-919.17 6080.62,-909.17 6070.62,-919.17 6060.62,-919.17 ; 6060.62,-759.17 6070.62,-759.17 6070.62,-769.17 6090.62,-769.17 6090.62,-759.17 6100.62,-759.17 6100.62,-739.17 6090.62,-739.17 6090.62,-729.17 6070.62,-729.17 6070.62,-739.17 6060.62,-739.17 6060.62,-759.17
  lines w15: 5987.5,-977.5 9866.47,-977.5 ; 5987.5,-377.5 9866.47,-377.5 ; 6538.38,-1127.5 6538.38,-227.5 ; 7236.19,-1127.5 7236.19,-227.5 ; 8581.79,-1127.5 8581.79,-227.5 ; 9087.67,-1127.5 9087.67,-227.5 ; 5987.5,-1127.5 9866.47,-1127.5 9866.47,-227.5 5987.5,-227.5 5987.5,-1127.5
  text "Symbol" at 6077.5,-332.5 h72
  text "Hit Count" at 6583.38,-332.5 h72
  text "Finished Hole Size" at 7281.19,-332.5 h72
  text "Plated" at 8626.79,-332.5 h72
  text "Hole Type" at 9132.67,-332.5 h72
  text "4" at 6583.38,-482.5 h60
  text "152.00mil (3.861mm)" at 7281.19,-482.5 h60
  text "NPTH" at 8626.79,-482.5 h60
  text "Round" at 9132.67,-482.5 h60
  text "5" at 6583.38,-632.5 h60
  text "7.87mil (0.200mm)" at 7281.19,-632.5 h60
  text "PTH" at 8626.79,-632.5 h60
  text "Round" at 9132.67,-632.5 h60
  text "A" at 6048.41,-642.49 h66.67
  text "16" at 6583.38,-782.5 h60
  text "28.00mil (0.711mm)" at 7281.19,-782.5 h60
  text "PTH" at 8626.79,-782.5 h60
  text "Round" at 9132.67,-782.5 h60
  text "53" at 6583.38,-932.5 h60
  text "16.00mil (0.406mm)" at 7281.19,-932.5 h60
  text "PTH" at 8626.79,-932.5 h60
  text "Round" at 9132.67,-932.5 h60
  text "78 Total" at 6583.38,-1082.5 h60
  text ".Layer_Name" at -73,-1708.49 h60

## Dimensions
5,100 to 3155,-40 on M2 Board Dimensions
150,3155 to 5,5 on M2 Board Dimensions
-650,-1250 to 350,-1250 on M2 Board Dimensions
